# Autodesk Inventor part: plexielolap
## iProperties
Created: 2015-01
Part Number: plexielolap
Document SubType Name: Modeling
Designer: Tulajdonos
Author: Tulajdonos
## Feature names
1. Kihúzás1 [Extrusion]
